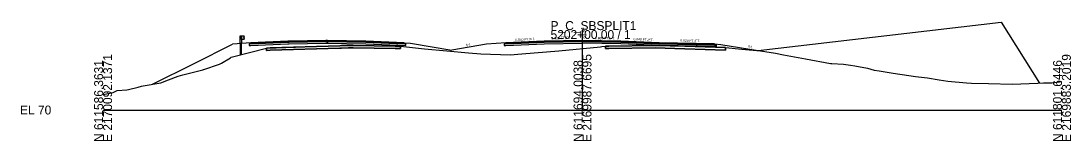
# Model space of a CAD drawing. Extents: x -26 to 1303, y -3010 to 12033.
# Drawn here: x 974.3 to 1302.8, y 2990.3 to 3027.8 of the extents above; entities that cross this region are included whole.
import ezdxf

# ---------------------------------------------------------------- set-up
doc = ezdxf.new("R2010")
doc.units = 0
for name, color, linetype in [('RD_GPK_XS_Cell', 7, 'Continuous'), ('RD_PD_Final_TrvlWay', 7, 'Continuous'), ('RD_Sketch10', 7, 'Continuous'), ('RD_XS_Base', 7, 'Continuous'), ('RD_XS_ExGround', 7, 'Continuous'), ('RD_XS_ExPaveRet', 7, 'Continuous'), ('RD_XS_GR', 7, 'Continuous'), ('RD_XS_Greenside', 7, 'Continuous'), ('RD_XS_Pave', 7, 'Continuous'), ('RD_XS_PaveOvlay_CP', 7, 'Continuous'), ('RD_XS_TieSlope', 7, 'Continuous'), ('RD_XS_TX_Elev_EX', 7, 'Continuous'), ('RD_XS_TX_Elev_PR', 7, 'Continuous'), ('RD_XS_TX_Slope', 7, 'Continuous')]:
    doc.layers.add(name, color=color, linetype=linetype)

msp = doc.modelspace()

# ---------------------------------------------------------------- linework, layer by layer
at = {"layer": 'RD_GPK_XS_Cell'}
for p, q in [((1150, 3000), (1150, 3025)), ((1000, 3000), (1150, 3000)), ((1150, 3000), (1300, 3000))]:
    msp.add_line(p, q, dxfattribs=at)
at = {"layer": 'RD_PD_Final_TrvlWay'}
msp.add_lwpolyline([(1043.33, 3017.21), (1043.33, 3020.82), (1042.83, 3020.78), (1042.83, 3017.21)], dxfattribs=at)
at = {"layer": 'RD_Sketch10'}
msp.add_lwpolyline([(1204.95, 3018.6), (1281, 3027.49), (1292.97, 3008.44)], dxfattribs=at)
at = {"layer": 'RD_XS_Base'}
for p, q in [((1046.2, 3020.73), (1045.71, 3020.71)), ((1045.71, 3020.71), (1045.71, 3020.7)), ((1045.71, 3020.7), (1045.71, 3020.21)), ((1045.71, 3020.21), (1046.2, 3020.23)), ((1046.21, 3020.73), (1046.2, 3020.73)), ((1046.2, 3020.23), (1046.21, 3020.23)), ((1057.82, 3021.19), (1046.21, 3020.73)), ((1046.21, 3020.23), (1057.82, 3020.69)), ((1058.21, 3021.21), (1057.82, 3021.19)), ((1057.82, 3020.69), (1058.21, 3020.71)), ((1069.67, 3021.44), (1058.21, 3021.21)), ((1058.21, 3020.71), (1069.67, 3020.94)), ((1070.21, 3021.45), (1069.67, 3021.44)), ((1069.67, 3020.94), (1070.21, 3020.95)), ((1070.21, 3021.6), (1070.21, 3021.61)), ((1070.21, 3021.61), (1070.21, 3021.58)), ((1070.21, 3021.45), (1070.21, 3021.61)), ((1070.21, 3021.61), (1070.21, 3021.61)), ((1070.21, 3021.61), (1070.21, 3021.61)), ((1070.21, 3021.61), (1070.21, 3020.95)), ((1070.21, 3021.45), (1070.21, 3021.6)), ((1070.21, 3021.58), (1070.21, 3020.95)), ((1070.21, 3021.43), (1070.21, 3021.45)), ((1070.21, 3020.95), (1070.21, 3021.45)), ((1070.21, 3021.45), (1070.21, 3021.45)), ((1070.21, 3021.45), (1070.21, 3021.45)), ((1070.21, 3021.45), (1070.21, 3021.45)), ((1082.21, 3021.21), (1070.21, 3021.45)), ((1070.21, 3020.95), (1070.21, 3021.43)), ((1070.21, 3020.95), (1070.21, 3020.95)), ((1070.21, 3020.95), (1070.21, 3020.95)), ((1070.21, 3020.95), (1082.21, 3020.71)), ((1094.21, 3020.73), (1082.21, 3021.21)), ((1082.21, 3020.71), (1094.71, 3020.21)), ((1084.21, 3021.13), (1084.21, 3021.13)), ((1084.21, 3020.63), (1084.21, 3020.63)), ((1094.71, 3020.71), (1094.21, 3020.73)), ((1094.21, 3020.73), (1094.21, 3020.73)), ((1094.71, 3020.21), (1094.71, 3020.71)), ((1094.71, 3020.71), (1094.71, 3020.71)), ((1126, 3020.73), (1125.5, 3020.71)), ((1125.5, 3020.71), (1125.5, 3020.71)), ((1125.5, 3020.71), (1125.5, 3020.21)), ((1125.5, 3020.21), (1126, 3020.23)), ((1138, 3021.21), (1126, 3020.73)), ((1126, 3020.73), (1126, 3020.73)), ((1126, 3020.23), (1138, 3020.71)), ((1126, 3020.23), (1126, 3020.23)), ((1136, 3021.13), (1136, 3021.13)), ((1136, 3020.63), (1136, 3020.63)), ((1150, 3021.45), (1138, 3021.21)), ((1138, 3020.71), (1150, 3020.95)), ((1150, 3020.95), (1150, 3021.61)), ((1150, 3021.61), (1150, 3021.61)), ((1150, 3021.61), (1150, 3021.61)), ((1150, 3021.61), (1150, 3021.45)), ((1150, 3021.45), (1150, 3021.45)), ((1150, 3021.45), (1162, 3021.21)), ((1150, 3021.45), (1150, 3021.45)), ((1150, 3020.95), (1150, 3021.45)), ((1150, 3021.45), (1150, 3021.45)), ((1150, 3021.45), (1150, 3021.45)), ((1162, 3020.71), (1150, 3020.95)), ((1150, 3020.95), (1150, 3020.95)), ((1150, 3020.95), (1150, 3020.95)), ((1162, 3021.21), (1162, 3021.21)), ((1162, 3021.21), (1174, 3020.73)), ((1174, 3020.23), (1162, 3020.71)), ((1162, 3020.71), (1162, 3020.71)), ((1174, 3020.73), (1174, 3020.73)), ((1174, 3020.73), (1191.3, 3020.38)), ((1191.8, 3019.87), (1174, 3020.23)), ((1174, 3020.23), (1174, 3020.23)), ((1191.3, 3020.38), (1191.3, 3020.38)), ((1191.3, 3020.38), (1191.8, 3020.37)), ((1191.8, 3020.37), (1191.8, 3020.37)), ((1191.8, 3020.37), (1191.8, 3019.87))]:
    msp.add_line(p, q, dxfattribs=at)
at = {"layer": 'RD_XS_ExGround'}
msp.add_lwpolyline([(1000, 3004.82), (1003.19, 3005.5), (1004.35, 3006.08), (1007.39, 3006.29), (1007.91, 3006.46), (1010.96, 3007.17), (1011.96, 3007.42), (1012.49, 3007.55), (1018.01, 3008.51), (1020.5, 3009.43), (1023.5, 3010.62), (1024.98, 3011.03), (1031.16, 3012.57), (1031.23, 3012.58), (1031.41, 3012.64), (1031.48, 3012.67), (1036.41, 3014.36), (1037.03, 3014.62), (1039.82, 3016.35), (1040.06, 3016.5), (1040.48, 3016.61), (1051.17, 3019.38), (1072.18, 3020.05), (1076.12, 3020.17), (1077.36, 3020.22), (1078.22, 3020.2), (1093.04, 3019.95), (1100.53, 3019.17), (1107.55, 3018.51), (1114.32, 3017.87), (1118.23, 3017.6), (1127.32, 3017.3), (1130.97, 3017.58), (1142.57, 3018.5), (1155.6, 3019.8), (1156.09, 3019.85), (1157.23, 3019.96), (1158.22, 3019.98), (1172.78, 3020.23), (1182.01, 3019.92), (1194.7, 3019.51), (1199.88, 3019.03), (1205.69, 3018.54), (1210.41, 3017.73), (1212.92, 3017.3), (1219.82, 3016.02), (1227.58, 3014.56), (1227.97, 3014.5), (1231.64, 3014.31), (1233.84, 3014.01), (1235.25, 3013.84), (1239.2, 3013.11), (1241.25, 3012.49), (1242.79, 3012.25), (1247.23, 3011.5), (1252.06, 3010.83), (1254.16, 3010.5), (1257.94, 3010.02), (1261.56, 3009.44), (1264.32, 3009.03), (1270.1, 3008.5), (1271.69, 3008.42), (1276.99, 3008.27), (1284.43, 3008.06), (1292.48, 3008.42), (1294.2, 3008.5), (1296.82, 3008.5), (1297.77, 3008.62), (1300, 3008.97)], dxfattribs=at)
at = {"layer": 'RD_XS_ExPaveRet'}
for points in [[(1091.33, 3019.98), (1093.04, 3019.95), (1093.04, 3019.31), (1093.04, 3019.2), (1091.33, 3019.23), (1078.22, 3019.45), (1077.79, 3019.46), (1077.36, 3019.47), (1076.73, 3019.44), (1074.62, 3019.38), (1074.03, 3019.36), (1052.29, 3018.67), (1051.27, 3018.64), (1051.17, 3018.63), (1051.17, 3018.63), (1051.17, 3018.63), (1051.17, 3018.67), (1051.17, 3019.38), (1051.17, 3019.38), (1051.17, 3019.38), (1051.27, 3019.39), (1052.29, 3019.42), (1074.03, 3020.11), (1074.62, 3020.13), (1076.73, 3020.19), (1077.36, 3020.22), (1077.79, 3020.21), (1078.22, 3020.2), (1091.33, 3019.98)], [(1078.22, 3020.2), (1077.79, 3020.21), (1077.36, 3020.22), (1076.73, 3020.19), (1074.62, 3020.13), (1074.03, 3020.11), (1052.29, 3019.42), (1051.27, 3019.39), (1051.17, 3019.38), (1051.17, 3019.38), (1051.17, 3018.67), (1051.17, 3018.63), (1051.17, 3018.63), (1051.27, 3018.64), (1052.29, 3018.67), (1074.03, 3019.36), (1074.62, 3019.38), (1076.73, 3019.44), (1077.36, 3019.47), (1077.79, 3019.46), (1078.22, 3019.45), (1091.33, 3019.23), (1093.04, 3019.2), (1093.04, 3019.31), (1093.04, 3019.95), (1091.33, 3019.98), (1078.22, 3020.2)], [(1194.7, 3019.51), (1194.7, 3019.51), (1194.7, 3018.76), (1194.7, 3018.76), (1194.7, 3018.76), (1182.01, 3019.17), (1182.01, 3019.17), (1172.78, 3019.48), (1172.78, 3019.48), (1158.22, 3019.23), (1158.22, 3019.23), (1157.23, 3019.21), (1157.23, 3019.21), (1157.23, 3019.21), (1157.23, 3019.96), (1157.23, 3019.96), (1158.22, 3019.98), (1158.22, 3019.98), (1172.78, 3020.23), (1172.78, 3020.23), (1182.01, 3019.92), (1182.01, 3019.92), (1194.7, 3019.51)], [(1182.01, 3019.92), (1172.78, 3020.23), (1158.22, 3019.98), (1157.23, 3019.96), (1157.23, 3019.96), (1157.23, 3019.21), (1157.23, 3019.21), (1158.22, 3019.23), (1172.78, 3019.48), (1182.01, 3019.17), (1194.7, 3018.76), (1194.7, 3019.51), (1182.01, 3019.92)]]:
    msp.add_lwpolyline(points, dxfattribs=at)
at = {"layer": 'RD_XS_GR'}
for p, q in [((1042.83, 3020.78), (1042.83, 3023.21)), ((1042.83, 3023.21), (1043.08, 3023.21)), ((1043.08, 3023.21), (1043.33, 3023.21)), ((1043.33, 3023.21), (1043.33, 3020.82)), ((1043.33, 3022.04), (1043.33, 3023.21)), ((1043.33, 3023.21), (1043.99, 3023.21)), ((1043.99, 3023.21), (1043.99, 3022.04)), ((1044, 3023.21), (1043.99, 3023.21)), ((1043.99, 3023.21), (1043.99, 3023.19)), ((1043.99, 3023.19), (1043.99, 3022.04)), ((1043.99, 3022.63), (1044.26, 3022.91)), ((1044, 3022.62), (1043.99, 3022.63)), ((1044.27, 3022.92), (1044, 3023.21)), ((1044.27, 3022.34), (1044, 3022.62)), ((1044.26, 3022.91), (1044.27, 3022.92)), ((1043.33, 3020.82), (1042.83, 3020.78)), ((1043.99, 3022.04), (1043.33, 3022.04)), ((1043.99, 3022.04), (1044.26, 3022.33)), ((1044.26, 3022.33), (1044.27, 3022.34))]:
    msp.add_line(p, q, dxfattribs=at)
at = {"layer": 'RD_XS_Greenside'}
for p, q in [((1028.54, 3014.6), (1040.52, 3020.59)), ((1096.21, 3020.89), (1109.07, 3018.74)), ((1120, 3020.57), (1109.07, 3018.74)), ((1193.3, 3020.54), (1204.95, 3018.6)), ((1015.47, 3008.07), (1028.54, 3014.6))]:
    msp.add_line(p, q, dxfattribs=at)
at = {"layer": 'RD_XS_Pave'}
for p, q in [((1057.82, 3021.51), (1046.21, 3021.05)), ((1057.82, 3021.35), (1046.21, 3020.89)), ((1046.21, 3020.89), (1057.82, 3021.35)), ((1046.21, 3020.73), (1057.82, 3021.19)), ((1046.21, 3021.05), (1046.21, 3021.04)), ((1046.21, 3021.04), (1046.21, 3020.89)), ((1046.21, 3020.89), (1046.21, 3020.89)), ((1046.21, 3020.89), (1046.21, 3020.73)), ((1058.21, 3021.53), (1057.82, 3021.51)), ((1058.21, 3021.37), (1057.82, 3021.35)), ((1057.82, 3021.35), (1058.21, 3021.37)), ((1057.82, 3021.19), (1058.21, 3021.21)), ((1069.67, 3021.76), (1058.21, 3021.53)), ((1069.67, 3021.6), (1058.21, 3021.37)), ((1058.21, 3021.37), (1069.67, 3021.6)), ((1058.21, 3021.21), (1069.67, 3021.44)), ((1070.21, 3021.77), (1069.67, 3021.76)), ((1070.21, 3021.61), (1069.67, 3021.6)), ((1069.67, 3021.6), (1070.21, 3021.61)), ((1069.67, 3021.44), (1070.21, 3021.45)), ((1082.21, 3021.53), (1070.21, 3021.77)), ((1070.21, 3021.77), (1070.21, 3021.77)), ((1070.21, 3021.77), (1070.21, 3021.77)), ((1070.21, 3021.6), (1070.21, 3021.61)), ((1070.21, 3021.61), (1070.21, 3021.6)), ((1070.21, 3021.45), (1070.21, 3021.61)), ((1070.21, 3021.61), (1070.21, 3021.61)), ((1070.21, 3021.61), (1070.21, 3021.61)), ((1070.21, 3021.61), (1070.21, 3021.61)), ((1070.21, 3021.61), (1070.21, 3021.61)), ((1070.21, 3021.61), (1082.21, 3021.37)), ((1082.21, 3021.37), (1070.21, 3021.61)), ((1070.21, 3021.61), (1070.21, 3021.61)), ((1070.21, 3021.61), (1070.21, 3021.61)), ((1070.21, 3021.61), (1070.21, 3021.45)), ((1070.21, 3021.45), (1070.21, 3021.6)), ((1070.21, 3021.6), (1070.21, 3021.45)), ((1070.21, 3021.45), (1070.21, 3021.45)), ((1070.21, 3021.45), (1070.21, 3021.45)), ((1070.21, 3021.45), (1082.21, 3021.21)), ((1094.21, 3021.05), (1082.21, 3021.53)), ((1082.21, 3021.37), (1094.21, 3020.89)), ((1094.21, 3020.89), (1082.21, 3021.37)), ((1082.21, 3021.21), (1094.21, 3020.73)), ((1084.21, 3021.45), (1084.21, 3021.45)), ((1084.21, 3021.29), (1084.21, 3021.29)), ((1084.21, 3021.29), (1084.21, 3021.29)), ((1084.21, 3021.13), (1084.21, 3021.13)), ((1094.21, 3020.89), (1094.21, 3021.05)), ((1094.21, 3021.05), (1094.21, 3021.05)), ((1094.21, 3020.73), (1094.21, 3020.89)), ((1094.21, 3020.89), (1094.21, 3020.89)), ((1138, 3021.53), (1126, 3021.05)), ((1138, 3021.37), (1126, 3020.89)), ((1126, 3020.89), (1138, 3021.37)), ((1126, 3020.73), (1138, 3021.21)), ((1126, 3021.05), (1126, 3021.05)), ((1126, 3021.05), (1126, 3020.89)), ((1126, 3020.89), (1126, 3020.89)), ((1126, 3020.89), (1126, 3020.73)), ((1136, 3021.45), (1136, 3021.45)), ((1136, 3021.29), (1136, 3021.29)), ((1136, 3021.29), (1136, 3021.29)), ((1136, 3021.13), (1136, 3021.13)), ((1150, 3021.77), (1138, 3021.53)), ((1150, 3021.61), (1138, 3021.37)), ((1138, 3021.37), (1150, 3021.61)), ((1138, 3021.21), (1150, 3021.45)), ((1162, 3021.53), (1150, 3021.77)), ((1150, 3021.77), (1150, 3021.77)), ((1150, 3021.77), (1150, 3021.77)), ((1150, 3021.45), (1150, 3021.61)), ((1150, 3021.61), (1150, 3021.61)), ((1150, 3021.61), (1150, 3021.61)), ((1150, 3021.61), (1150, 3021.61)), ((1150, 3021.61), (1150, 3021.61)), ((1150, 3021.61), (1162, 3021.37)), ((1162, 3021.37), (1150, 3021.61)), ((1150, 3021.61), (1150, 3021.61)), ((1150, 3021.61), (1150, 3021.61)), ((1150, 3021.61), (1150, 3021.61)), ((1150, 3021.61), (1150, 3021.45)), ((1150, 3021.45), (1150, 3021.45)), ((1150, 3021.45), (1150, 3021.45)), ((1150, 3021.45), (1150, 3021.45)), ((1150, 3021.45), (1162, 3021.21)), ((1174, 3021.05), (1162, 3021.53)), ((1162, 3021.53), (1162, 3021.53)), ((1162, 3021.37), (1162, 3021.37)), ((1162, 3021.37), (1174, 3020.89)), ((1174, 3020.89), (1162, 3021.37)), ((1162, 3021.37), (1162, 3021.37)), ((1162, 3021.21), (1162, 3021.21)), ((1162, 3021.21), (1174, 3020.73)), ((1191.3, 3020.7), (1174, 3021.05)), ((1174, 3021.05), (1174, 3021.05)), ((1174, 3020.89), (1174, 3020.89)), ((1174, 3020.89), (1191.3, 3020.54)), ((1191.3, 3020.54), (1174, 3020.89)), ((1174, 3020.89), (1174, 3020.89)), ((1174, 3020.73), (1191.3, 3020.38)), ((1174, 3020.73), (1174, 3020.73)), ((1191.3, 3020.54), (1191.3, 3020.7)), ((1191.3, 3020.7), (1191.3, 3020.7)), ((1191.3, 3020.38), (1191.3, 3020.54)), ((1191.3, 3020.54), (1191.3, 3020.54))]:
    msp.add_line(p, q, dxfattribs=at)
at = {"layer": 'RD_XS_PaveOvlay_CP'}
for p, q in [((1046.21, 3021.05), (1058.21, 3021.53)), ((1058.21, 3021.53), (1070.21, 3021.77)), ((1070.21, 3021.77), (1082.21, 3021.53)), ((1082.21, 3021.53), (1094.21, 3021.05)), ((1138, 3021.53), (1126, 3021.05)), ((1136, 3021.45), (1136, 3021.45)), ((1150, 3021.77), (1138, 3021.53)), ((1162, 3021.53), (1150, 3021.77)), ((1150, 3021.77), (1150, 3021.77)), ((1150, 3021.77), (1150, 3021.77)), ((1174, 3021.05), (1162, 3021.53)), ((1162, 3021.53), (1162, 3021.53)), ((1191.3, 3020.7), (1174, 3021.05)), ((1174, 3021.05), (1174, 3021.05))]:
    msp.add_line(p, q, dxfattribs=at)
at = {"layer": 'RD_XS_TieSlope'}
for p, q in [((1046.21, 3021.05), (1040.52, 3020.59)), ((1094.21, 3021.05), (1096.21, 3020.89)), ((1126, 3021.05), (1120, 3020.57)), ((1191.3, 3020.7), (1193.3, 3020.54))]:
    msp.add_line(p, q, dxfattribs=at)

# ---------------------------------------------------------------- texts
at = {"layer": 'RD_GPK_XS_Cell'}
for s, p in [('P_C_SBSPLIT1', (1140, 3025)), ('5202+00.00 / 1', (1140, 3022.2)), ('EL 70', (974, 2998.6))]:
    msp.add_text(s, height=2.8, dxfattribs=at).set_placement(p)
for s, p in [('E 2170092.1371', (1002.8, 2990)), ('E 2169987.6695', (1152.8, 2990)), ('E 2169883.2019', (1302.8, 2990)), ('N 611586.3631', (1000, 2990)), ('N 611694.0038', (1150, 2990)), ('N 611801.6446', (1300, 2990))]:
    msp.add_text(s, height=2.8, rotation=90, dxfattribs=at).set_placement(p)
at = {"layer": 'RD_XS_TX_Elev_EX'}
msp.add_text('89.24', height=0.6, rotation=90, dxfattribs=at).set_placement((1149.68, 3022.75))
at = {"layer": 'RD_XS_TX_Elev_PR'}
msp.add_text('91.77', height=1, rotation=90, dxfattribs=at).set_placement((1151.2, 3022.33))
at = {"layer": 'RD_XS_TX_Slope'}
for s, rotation, p in [('0.040 FT./FT.', 2.2906, (1128.93, 3021.6)), ('0.020 FT./FT.', 1.1458, (1140.27, 3022.08)), ('0.020 FT./FT.', 358.8542, (1153.94, 3022.12)), ('0.040 FT./FT.', 357.7094, (1165.94, 3021.81)), ('6:1', 9.4642, (1113.57, 3019.91)), ('0.020 FT./FT.', 358.8542, (1180.59, 3021.35)), ('6:1', 350.5377, (1201.72, 3019.53))]:
    msp.add_text(s, height=0.75, rotation=rotation, dxfattribs=at).set_placement(p)

doc.saveas('drawing.dxf')
